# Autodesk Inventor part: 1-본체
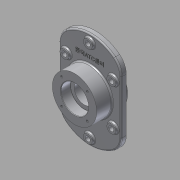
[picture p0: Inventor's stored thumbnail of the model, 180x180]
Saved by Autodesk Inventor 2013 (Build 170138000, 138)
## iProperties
Created: 2015-02
Part Number: 1-본체
Material: 알루미늄 6061
Document SubType Name: Modeling
Designer: kb543-17
Density: 2.71 g/cm^3
Mass: 1661.1 g
Surface Area: 941.99 cm^2
Volume: 612.952 cm^3
Author: kb543-17
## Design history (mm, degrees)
sketch "스케치1"
  geometry: C1 r 50 at (0, 0); 1 further point
  constraints: 1 centre point, 1 coincident
  dimensions: "d0" = 100 diameter of C1
extrude "돌출1" new body sketch "스케치1" stored distance "d2" = 70; taper "d3" = 0 deg
node "작업 평면1"
sketch "스케치5"
  geometry: L1 (-70, 60)-(-70, -60); L2 (70, 60)-(70, -60); L3 (-70, 60)-(70, 60); L4 (0, 0)-(0, 165.708); L5 (-85.236, 110)-(82.806, 110); L6 (-71.387, -110)-(86.499, -110); L7 (0, 0)-(31.667, 0); A1 r 88.979 centre (0, 21.021) between (54.875, 91.064) and (-54.875, 91.064); A2 r 39.462 centre (-30.538, 60) between (-54.875, 91.064) and (-70, 60); A3 r 39.462 centre (30.538, 60) between (70, 60) and (54.875, 91.064); A4 r 88.979 centre (0, -21.021) between (-54.875, -91.064) and (54.875, -91.064); A5 r 39.462 centre (-30.538, -60) between (-70, -60) and (-54.875, -91.064); A6 r 39.462 centre (30.538, -60) between (54.875, -91.064) and (70, -60)
  constraints: 14 end point, 12 point on circle, 6 centre point, 6 tangent, 4 equal radius, 4 parallel, 2 perpendicular, 2 point on line, 1 vertical, 1 vertical alignment
  dimensions: "d128" = 70 distance from line of L4.start L1; "d129" = 60 vertical distance of L1.start L4.start; "d130" = 120 distance of L1.start L1.end; "d131" = 70 distance from line of L2 L4.start; "d132" = 60 vertical distance of L2.start L4.start; "d133" = 120 distance of L2.start L2.end (derived); "d134" = 50 distance from line of L2.start L5; "d135" = 50 distance from line of L2.end L6; "d136" = 88.97858 radius of A1
extrude "돌출4" join sketch "스케치5" distance "d137" = 12; taper "d138" = 0 deg
hole "구멍11" diameter "d141" = 45; stored, may be unused: countersink angle "d145" = 90 deg, drill point angle "d147" = 0 deg; dims "d139" = 10, "d140" = 10, "d142" = 11, "d143" = 4, "d144" = 2, "d146" = 13
hole "구멍12" diameter "d150" = 62; stored, may be unused: countersink angle "d154" = 90 deg, drill point angle "d156" = 0 deg; dims "d148" = 10, "d149" = 10, "d151" = 11, "d152" = 4, "d153" = 2, "d155" = 22
hole "구멍13" diameter "d159" = 62; stored, may be unused: countersink angle "d163" = 90 deg, drill point angle "d165" = 0 deg; dims "d157" = 10, "d158" = 10, "d160" = 11, "d161" = 4, "d162" = 2, "d164" = 22
sketch "스케치6"
  geometry: A1 r 41 centre (0, 0) between (0, 41) and (-40.808, 3.967); 2 further points
  constraints: 3 point on circle, 1 centre point, 1 coincident, 1 vertical alignment
  dimensions: "d166" = 45 deg dimension on point (0, 0) point (-28.991, 28.991) A1.start; "d167" = 41 radius of A1
hole "구멍14" sketch "스케치6" at (-28.991, 28.991) diameter "d169" = 4.917; stored, may be unused: countersink angle "d173" = 90 deg, drill point angle "d175" = 118 deg; dims "d170" = 10, "d171" = 4, "d172" = 2, "d174" = 13
sketch "스케치7"
  geometry: L1 (-70, -60)-(-70, 60) reference; L2 (70, 60)-(70, -60) reference; L3 (-53, 60)-(-53, -60); L4 (53, -60)-(53, 60); L5 (-53, 46.5)-(53, 46.5); L6 (-105.828, -46.5)-(53, -46.5); C1 r 22.5 at (0, 0) reference; C2 r 50 at (0, 0) reference; C3 r 10 at (0, 93); C4 r 10 at (-53, 46.5); C5 r 10 at (-53, -46.5); C6 r 10 at (0, -93); C7 r 10 at (53, -46.5); C8 r 10 at (53, 46.5); A1 r 39.462 centre (30.538, -60) between (54.875, -91.064) and (70, -60) reference; A2 r 88.979 centre (0, -21.021) between (-54.875, -91.064) and (54.875, -91.064) reference; A3 r 39.462 centre (-30.538, -60) between (-70, -60) and (-54.875, -91.064) reference; A4 r 39.462 centre (-30.538, 60) between (-54.875, 91.064) and (-70, 60) reference; A5 r 88.979 centre (0, 21.021) between (54.875, 91.064) and (-54.875, 91.064) reference; A6 r 39.462 centre (30.538, 60) between (70, 60) and (54.875, 91.064) reference; A7 r 22.462 centre (-30.538, 60) between (-44.391, 77.681) and (-53, 60); A8 r 22.462 centre (-30.538, -60) between (-53, -60) and (-44.391, -77.681); A9 r 71.979 centre (0, -21.021) between (-44.391, -77.681) and (44.391, -77.681); A10 r 22.462 centre (30.538, -60) between (44.391, -77.681) and (53, -60); A11 r 22.462 centre (30.538, 60) between (53, 60) and (44.391, 77.681); A12 r 71.979 centre (0, 21.021) between (44.391, 77.681) and (-44.391, 77.681); 2 further points
  constraints: 13 point on circle, 12 centre point, 8 end point, 5 equal radius, 4 point on line, 1 coincident, 1 parallel, 1 perpendicular, 1 vertical alignment, 7 other
  dimensions: "d179" = 17 distance between parallel lines of L3 L1; "d183" = 20 diameter of C3; "d184" = 20 diameter of C4 (derived); "d185" = 17 distance from line of L1 L5.start (derived)
extrude "돌출5" join sketch "스케치7" distance "d186" = 5; taper "d187" = 0 deg
hole "구멍15" diameter "d190" = 11; stored, may be unused: countersink angle "d194" = 90 deg, drill point angle "d196" = 118 deg; dims "d188" = 10, "d189" = 10, "d191" = 11, "d192" = 4, "d193" = 2, "d195" = 13
hole "구멍16" diameter "d199" = 11; stored, may be unused: countersink angle "d203" = 90 deg, drill point angle "d205" = 118 deg; dims "d197" = 10, "d198" = 10, "d200" = 11, "d201" = 4, "d202" = 2, "d204" = 13
hole "구멍17" diameter "d208" = 11; stored, may be unused: countersink angle "d212" = 90 deg, drill point angle "d214" = 118 deg; dims "d206" = 10, "d207" = 10, "d209" = 11, "d210" = 4, "d211" = 2, "d213" = 13
hole "구멍18" diameter "d217" = 11; stored, may be unused: countersink angle "d221" = 90 deg, drill point angle "d223" = 118 deg; dims "d215" = 10, "d216" = 10, "d218" = 11, "d219" = 4, "d220" = 2, "d222" = 13
hole "구멍19" diameter "d226" = 11; stored, may be unused: countersink angle "d230" = 90 deg, drill point angle "d232" = 118 deg; dims "d224" = 10, "d225" = 10, "d227" = 11, "d228" = 4, "d229" = 2, "d231" = 13
hole "구멍20" diameter "d235" = 11; stored, may be unused: countersink angle "d239" = 90 deg, drill point angle "d241" = 118 deg; dims "d233" = 10, "d234" = 10, "d236" = 11, "d237" = 4, "d238" = 2, "d240" = 13
fillet "모깎기3" dims "d242" = 3, "d243" = 0.3
chamfer "모따기2" distance "d244" = 1; stored, may be unused: second distance "d245" = 2, angle "d246" = 45 deg
sketch "스케치8"
  geometry: 2 further points
  constraints: 1 vertical alignment, 1 other
  dimensions: "d247" = 65 distance of point (0, 65) point (0, 0)
feature "엠보싱1" sketch "스케치8" dims "d25" = 2, "d248" = 1, "d249" = 0
sketch "스케치2"
  geometry: L1 (-70, 60)-(-70, -60); L2 (70, -60)-(70, 60); L3 (-70, 60)-(70, 60); L4 (70, -60)-(-70, -60); L5 (0, 0)-(31.591, 0); L6 (-83.343, 110)-(87.56, 110); L7 (-64.354, -110)-(81.564, -110); L8 (0, 217.088)-(0, -206.065); C1 r 17 at (-53, 60); C2 r 17 at (53, 62.823)
  constraints: 20 end point, 4 parallel, 2 centre point, 2 perpendicular, 2 point on line, 2 tangent, 1 vertical
  dimensions: "d5" = 140 distance between parallel lines of L2 L1; "d7" = 70 distance from line of L2 L5.start (= 0.5 x d5); "d9" = 120 distance of L2.end L2.start; "d14" = 50 distance between parallel lines of L6 L3; "d15" = 50 distance between parallel lines of L4 L7; "d16" = 220 distance between parallel lines of L7 L6 (derived); "d126" = 34 diameter of C1; "d127" = 34 diameter of C2
extrude "돌출2" join sketch "스케치2" distance "d18" = 12; taper "d19" = 0 deg
hole "구멍1" diameter "d22" = 45; stored, may be unused: countersink angle "d26" = 90 deg, drill point angle "d28" = 118 deg; dims "d20" = 10, "d21" = 10, "d23" = 6, "d24" = 4, "d25" = 2, "d27" = 8
hole "구멍2" diameter "d31" = 62; stored, may be unused: countersink angle "d35" = 90 deg, drill point angle "d37" = 0 deg; dims "d29" = 10, "d30" = 10, "d32" = 6, "d33" = 4, "d34" = 2, "d36" = 22
hole "구멍3" diameter "d40" = 62; stored, may be unused: countersink angle "d44" = 90 deg, drill point angle "d46" = 0 deg; dims "d38" = 10, "d39" = 10, "d41" = 6, "d42" = 4, "d43" = 2, "d45" = 22
sketch "스케치3"
  geometry: A1 r 41 centre (0, 0) between (0, 41) and (-39.842, 9.674); 2 further points
  constraints: 3 point on circle, 2 vertical alignment, 1 centre point, 1 coincident
  dimensions: "d47" = 45 deg dimension on point (0, 0) point (-28.991, 28.991) A1.start; "d48" = 41 radius of A1
hole "구멍4" sketch "스케치3" at (-28.991, 28.991) diameter "d50" = 4.917; stored, may be unused: countersink angle "d54" = 90 deg, drill point angle "d56" = 118 deg; dims "d51" = 10, "d52" = 4, "d53" = 2, "d55" = 13
sketch "스케치4"
  geometry: L1 (70, -59.495)-(70, 59.495) reference; L2 (-70, 59.495)-(-70, -59.495) reference; L3 (53, -56.19)-(53, 62.799); L4 (-53, 59.495)-(-53, -59.495); L5 (-53, -53)-(53, -53); L6 (53, -53)-(53, 53); L7 (53, 53)-(-53, 53); L8 (-53, 53)-(-53, -53); L9 (-53, -53)-(53, 53); L10 (53, -53)-(-53, 53); C1 r 10 at (0, 93); C2 r 10 at (-53, 53); C3 r 10 at (53, 53); C4 r 10 at (-53, -53); C5 r 10 at (53, -53); C6 r 10 at (0, -93); A1 r 74 centre (0, 36) between (69.831, 60.487) and (-69.831, 60.487) reference; A2 r 74 centre (0, -36) between (-69.831, -60.487) and (69.831, -60.487) reference; A3 r 57 centre (0, 36) between (53.789, 54.862) and (-53.789, 54.862); A4 r 57 centre (0, -36) between (-53.789, -54.862) and (53.789, -54.862); 3 further points
  constraints: 16 end point, 8 centre point, 6 coincident, 6 point on circle, 5 equal radius, 4 parallel, 2 midpoint, 2 perpendicular, 2 vertical alignment, 1 collinear, 1 horizontal
  dimensions: "d60" = 17 distance between parallel lines of L4 L2; "d61" = 17 distance between parallel lines of L1 L3; "d62" = 17 radial gap between concentric circles of A3 A1; "d63" = 17 radial gap between concentric circles of A4 A2; "d64" = 20 diameter of C1
extrude "돌출3" join sketch "스케치4" distance "d65" = 5; taper "d66" = 0 deg
hole "구멍5" diameter "d69" = 11; stored, may be unused: countersink angle "d73" = 90 deg, drill point angle "d75" = 0 deg; dims "d67" = 10, "d68" = 10, "d70" = 11, "d71" = 4, "d72" = 2, "d74" = 13
hole "구멍6" diameter "d78" = 11; stored, may be unused: countersink angle "d82" = 90 deg, drill point angle "d84" = 0 deg; dims "d76" = 10, "d77" = 10, "d79" = 11, "d80" = 4, "d81" = 2, "d83" = 13
hole "구멍7" diameter "d87" = 11; stored, may be unused: countersink angle "d91" = 90 deg, drill point angle "d93" = 0 deg; dims "d85" = 10, "d86" = 10, "d88" = 11, "d89" = 4, "d90" = 2, "d92" = 13
hole "구멍8" diameter "d96" = 11; stored, may be unused: countersink angle "d100" = 90 deg, drill point angle "d102" = 0 deg; dims "d94" = 10, "d95" = 10, "d97" = 11, "d98" = 4, "d99" = 2, "d101" = 13
hole "구멍9" diameter "d105" = 11; stored, may be unused: countersink angle "d109" = 90 deg, drill point angle "d111" = 0 deg; dims "d103" = 10, "d104" = 10, "d106" = 11, "d107" = 4, "d108" = 2, "d110" = 13
hole "구멍10" diameter "d114" = 11; stored, may be unused: countersink angle "d118" = 90 deg, drill point angle "d120" = 0 deg; dims "d112" = 10, "d113" = 10, "d115" = 11, "d116" = 4, "d117" = 2, "d119" = 13
chamfer "모따기1" distance "d121" = 1; stored, may be unused: second distance "d122" = 2, angle "d123" = 45 deg
fillet "모깎기1" dims "d124" = 0.3
fillet "모깎기2" dims "d125" = 3
node "솔리드1"
pattern_circular "원형 패턴2" dims angle "d177" = 360 deg
mirror "대칭2"
pattern_circular "원형 패턴1" dims angle "d58" = 360 deg
mirror "대칭1"
node "절단 모서리 투영1"
other parameters: "d4" = -23
